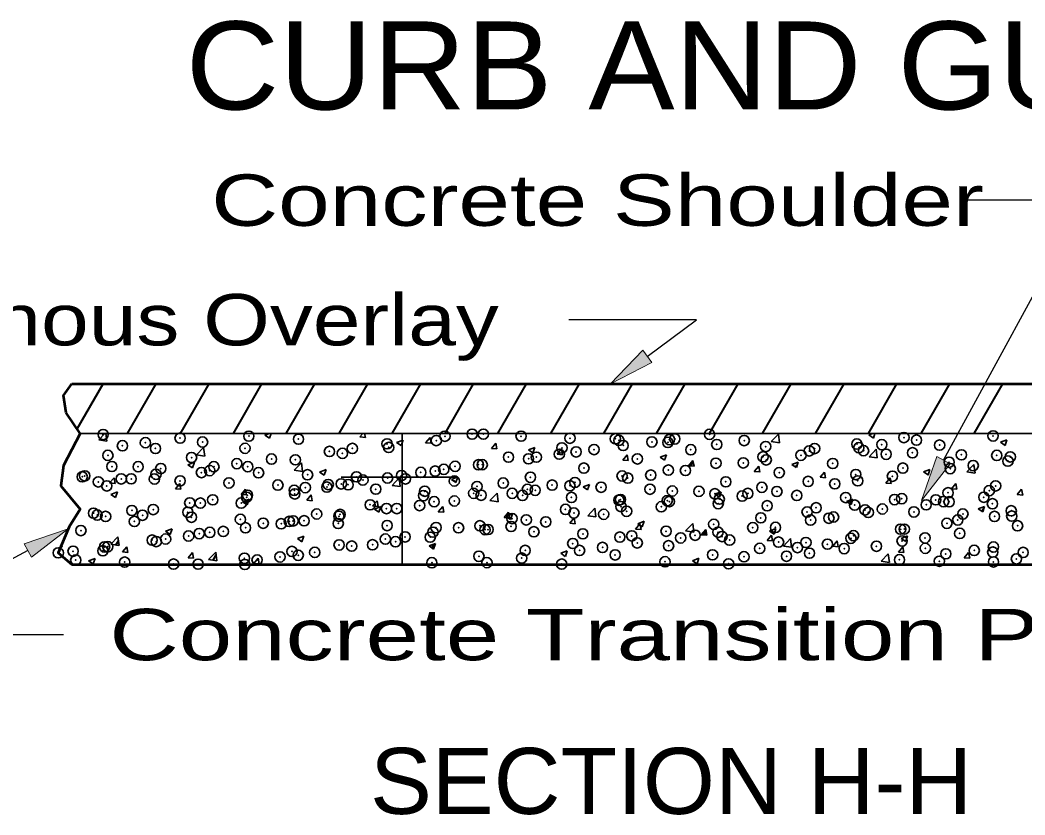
# Model space of a CAD drawing. Extents: x 14 to 49.3, y 28 to 50.
# Drawn here: x 25.568 to 28.309, y 37.153 to 39.319 of the extents above; entities that cross this region are included whole.
import ezdxf

# ---------------------------------------------------------------- set-up
doc = ezdxf.new("R2010")
doc.units = 0
doc.header["$LTSCALE"] = 0.056
doc.header["$PDMODE"] = 32
doc.header["$PDSIZE"] = 0.028
doc.layers.add('1', color=7, linetype='Continuous', lineweight=35)
doc.layers.add('3', color=7, linetype='Continuous', lineweight=13)

msp = doc.modelspace()

# ---------------------------------------------------------------- hatches: boundary and pattern name
at = {"layer": '3'}
for points in [[(27.29108, 38.38558), (27.26625, 38.419), (27.17842, 38.32767), (27.17842, 38.32767)], [(28.10483, 38.1095), (28.06825, 38.12942), (28.02667, 38.00975), (28.02667, 38.00975)], [(25.57942, 37.89183), (25.59917, 37.85517), (25.69933, 37.93283), (25.69933, 37.93283)]]:
    msp.add_hatch(color=256, dxfattribs=at).paths.add_polyline_path(points)

# ---------------------------------------------------------------- linework, layer by layer
at = {"layer": '1', "lineweight": 53}
msp.add_line((25.70917, 38.32767), (29.27625, 38.32767), dxfattribs=at)
at = {"layer": '1', "lineweight": 40}
for p, q in [((25.72367, 38.20467), (25.79467, 38.32767)), ((25.861, 38.1925), (25.939, 38.32767)), ((26.00533, 38.1925), (26.08333, 38.32767)), ((26.14967, 38.1925), (26.22767, 38.32767)), ((26.294, 38.1925), (26.372, 38.32767)), ((26.43833, 38.1925), (26.51633, 38.32767)), ((26.58267, 38.1925), (26.66067, 38.32767)), ((26.727, 38.1925), (26.805, 38.32767)), ((26.87133, 38.1925), (26.94933, 38.32767)), ((27.01567, 38.1925), (27.09367, 38.32767)), ((27.16, 38.1925), (27.238, 38.32767)), ((27.30433, 38.1925), (27.38233, 38.32767)), ((27.44875, 38.1925), (27.52667, 38.32767)), ((27.59308, 38.1925), (27.67108, 38.32767)), ((27.73742, 38.1925), (27.81542, 38.32767)), ((27.88175, 38.1925), (27.95975, 38.32767)), ((28.02608, 38.1925), (28.10408, 38.32767)), ((28.17042, 38.1925), (28.24842, 38.32767)), ((27.39742, 38.10375), (27.404, 38.11517)), ((27.684, 38.10008), (27.688, 38.10708)), ((26.18325, 38.00075), (26.18975, 38.012)), ((28.19192, 37.97983), (28.19767, 37.98983)), ((27.43317, 37.91558), (27.439, 37.92567)), ((25.8295, 37.888), (25.83625, 37.89958)), ((26.69117, 37.8805), (26.69725, 37.89092)), ((26.09442, 37.84692), (26.10267, 37.86117))]:
    msp.add_line(p, q, dxfattribs=at)
at = {"layer": '1'}
for p, q in [((29.27625, 38.1925), (25.73192, 38.1925)), ((25.78233, 38.17508), (25.79908, 38.1925)), ((25.80458, 38.17158), (25.80217, 38.1925)), ((26.23583, 38.18767), (26.24858, 38.1925)), ((26.23583, 38.18767), (26.24825, 38.17925)), ((26.24825, 38.17925), (26.25275, 38.1925)), ((26.49475, 38.18275), (26.503, 38.1925)), ((26.49475, 38.18275), (26.50967, 38.18142)), ((26.50967, 38.18142), (26.50767, 38.1925)), ((26.61042, 38.1925), (26.61042, 37.83492)), ((26.67408, 38.16708), (26.68608, 38.18142)), ((26.689, 38.16575), (26.68608, 38.18142)), ((27.61683, 38.17033), (27.63633, 38.19058)), ((27.63908, 38.16683), (27.63633, 38.19058)), ((27.883, 38.18817), (27.89433, 38.1925)), ((27.883, 38.18817), (27.89542, 38.17975)), ((27.89542, 38.17975), (27.89975, 38.1925)), ((25.78233, 38.17508), (25.80458, 38.17158)), ((26.04917, 38.13367), (26.06858, 38.154)), ((26.07142, 38.13025), (26.06858, 38.154)), ((26.59508, 38.16758), (26.61258, 38.17433)), ((26.59508, 38.16758), (26.6075, 38.15925)), ((26.6075, 38.15917), (26.61258, 38.17433)), ((26.67408, 38.16708), (26.689, 38.16575)), ((26.85342, 38.15133), (26.86542, 38.16575)), ((26.86833, 38.15), (26.86542, 38.16575)), ((26.95433, 38.14758), (26.97183, 38.15433)), ((26.96683, 38.13917), (26.97192, 38.15433)), ((27.61683, 38.17033), (27.63908, 38.16683)), ((28.24225, 38.16817), (28.25975, 38.17483)), ((28.24225, 38.16817), (28.25467, 38.15975)), ((28.25475, 38.15975), (28.25975, 38.17483)), ((26.04917, 38.13367), (26.07133, 38.13025)), ((26.85342, 38.15133), (26.86833, 38.15008)), ((26.95433, 38.14758), (26.96683, 38.13917)), ((27.03267, 38.13567), (27.04475, 38.15)), ((27.03267, 38.13567), (27.04767, 38.13433)), ((27.04767, 38.13433), (27.04475, 38.15)), ((27.212, 38.12), (27.22408, 38.13433)), ((27.22692, 38.11867), (27.22408, 38.13433)), ((27.31367, 38.12758), (27.33117, 38.13425)), ((27.31367, 38.12758), (27.32608, 38.11917)), ((27.32608, 38.11917), (27.33117, 38.13425)), ((27.88367, 38.12892), (27.90317, 38.14925)), ((27.88367, 38.12892), (27.90592, 38.1255)), ((27.90592, 38.1255), (27.90317, 38.14925)), ((26.02575, 38.107), (26.04325, 38.11375)), ((26.02575, 38.107), (26.03817, 38.09858)), ((26.03817, 38.09858), (26.04325, 38.11367)), ((26.03817, 38.09858), (26.04325, 38.11367)), ((26.31592, 38.09233), (26.33542, 38.11258)), ((26.33817, 38.08883), (26.33542, 38.11258)), ((27.212, 38.12), (27.22692, 38.11867)), ((27.39133, 38.10425), (27.40333, 38.11867)), ((27.39133, 38.10425), (27.40625, 38.103)), ((27.40625, 38.103), (27.40342, 38.11867)), ((27.57067, 38.08858), (27.58267, 38.103)), ((27.58558, 38.08725), (27.58267, 38.10292)), ((27.67292, 38.1075), (27.69042, 38.11425)), ((27.67292, 38.1075), (27.68533, 38.09917)), ((27.68542, 38.09917), (27.69042, 38.11425)), ((28.1505, 38.08758), (28.16992, 38.10783)), ((28.17275, 38.08408), (28.16992, 38.10783)), ((25.81217, 38.05742), (25.82425, 38.07183)), ((25.82708, 38.05608), (25.82425, 38.07175)), ((26.31592, 38.09233), (26.33817, 38.08883)), ((26.385, 38.087), (26.4025, 38.09367)), ((26.385, 38.087), (26.3975, 38.07858)), ((26.3975, 38.07858), (26.40258, 38.09367)), ((26.44383, 38.07333), (26.76192, 38.07333)), ((26.74433, 38.06692), (26.76183, 38.07367)), ((26.75675, 38.05858), (26.76183, 38.07367)), ((27.57067, 38.08858), (27.58558, 38.08733)), ((27.74992, 38.07292), (27.762, 38.08725)), ((27.74992, 38.07292), (27.76492, 38.07158)), ((27.76492, 38.07158), (27.762, 38.08725)), ((27.92925, 38.05725), (27.94133, 38.07158)), ((27.94425, 38.05592), (27.94133, 38.07158)), ((28.03225, 38.0875), (28.04975, 38.09425)), ((28.03225, 38.0875), (28.04467, 38.07917)), ((28.04467, 38.07908), (28.04975, 38.09425)), ((28.1505, 38.08758), (28.17267, 38.08408)), ((25.81217, 38.05742), (25.82708, 38.05617)), ((25.9915, 38.04175), (26.0035, 38.05608)), ((26.00642, 38.04042), (26.00358, 38.05608)), ((26.58275, 38.05092), (26.60225, 38.07125)), ((26.58275, 38.05092), (26.605, 38.0475)), ((26.605, 38.0475), (26.60225, 38.07125)), ((26.74433, 38.06692), (26.75675, 38.05858)), ((27.10358, 38.04692), (27.12108, 38.05367)), ((27.10358, 38.04692), (27.116, 38.0385)), ((27.116, 38.0385), (27.12108, 38.05367)), ((27.92925, 38.05725), (27.94425, 38.05592)), ((28.10858, 38.0415), (28.12067, 38.05592)), ((28.1235, 38.04025), (28.12067, 38.05592)), ((25.81567, 38.02633), (25.83317, 38.03308)), ((25.81567, 38.02633), (25.82817, 38.018)), ((25.82817, 38.018), (25.83317, 38.03308)), ((25.9915, 38.04175), (26.00642, 38.04042)), ((26.17083, 38.02608), (26.18283, 38.04042)), ((26.17083, 38.02608), (26.18575, 38.02475)), ((26.18575, 38.02475), (26.18283, 38.04042)), ((26.35008, 38.01033), (26.36217, 38.02475)), ((26.36508, 38.00908), (26.36217, 38.02475)), ((26.84958, 38.00958), (26.869, 38.02983)), ((26.87183, 38.00608), (26.86908, 38.02983)), ((27.46292, 38.02692), (27.48042, 38.03358)), ((27.46292, 38.02692), (27.47533, 38.0185)), ((27.47533, 38.0185), (27.48042, 38.03358)), ((28.10858, 38.0415), (28.1235, 38.04025)), ((28.28792, 38.02583), (28.29992, 38.04025)), ((28.28792, 38.02583), (28.30283, 38.02458)), ((28.30283, 38.0245), (28.29992, 38.04017)), ((26.175, 38.00633), (26.1925, 38.01308)), ((26.175, 38.00633), (26.18742, 37.99792)), ((26.18742, 37.99792), (26.1925, 38.01308)), ((26.35008, 38.01033), (26.36508, 38.00908)), ((26.52942, 37.99467), (26.5415, 38.00908)), ((26.52942, 37.99467), (26.54442, 37.99342)), ((26.53425, 37.98633), (26.55175, 37.993)), ((26.54442, 37.99333), (26.5415, 38.009)), ((26.54667, 37.97792), (26.55175, 37.993)), ((26.70875, 37.979), (26.72083, 37.99333)), ((26.72367, 37.97767), (26.72083, 37.99333)), ((26.84958, 38.00958), (26.87183, 38.00608)), ((27.82217, 38.00692), (27.83967, 38.01358)), ((27.82217, 38.00692), (27.83458, 37.9985)), ((27.83458, 37.9985), (27.83967, 38.01358)), ((28.18142, 37.98683), (28.19892, 37.99358)), ((28.19392, 37.9785), (28.19892, 37.99358)), ((26.53425, 37.98633), (26.54667, 37.97792)), ((26.70875, 37.979), (26.72367, 37.97767)), ((26.88808, 37.96333), (26.90008, 37.97767)), ((26.88808, 37.96333), (26.903, 37.962)), ((26.8935, 37.96633), (26.91108, 37.973)), ((26.8935, 37.96633), (26.906, 37.95792)), ((26.903, 37.962), (26.90008, 37.97767)), ((26.906, 37.95792), (26.91108, 37.973)), ((27.06742, 37.94758), (27.07942, 37.962)), ((27.08233, 37.94633), (27.07942, 37.962)), ((27.11642, 37.96817), (27.13583, 37.9885)), ((27.11642, 37.96817), (27.13858, 37.96475)), ((27.13858, 37.96475), (27.13583, 37.98842)), ((28.18142, 37.98683), (28.19392, 37.9785)), ((27.06742, 37.94758), (27.08233, 37.94633)), ((27.24667, 37.93192), (27.25875, 37.94633)), ((27.25283, 37.94625), (27.27033, 37.953)), ((27.25283, 37.94625), (27.26525, 37.93792)), ((27.26167, 37.93058), (27.25875, 37.94625)), ((27.26525, 37.93792), (27.27033, 37.953)), ((27.38317, 37.92675), (27.40267, 37.94708)), ((27.40542, 37.92333), (27.40267, 37.94708)), ((25.8155, 37.89017), (25.83492, 37.91042)), ((25.83775, 37.88667), (25.83492, 37.91042)), ((25.96492, 37.92567), (25.98242, 37.93242)), ((25.96492, 37.92567), (25.97733, 37.91733)), ((25.97733, 37.91733), (25.98242, 37.93242)), ((26.32417, 37.90567), (26.34167, 37.91242)), ((26.33667, 37.89725), (26.34175, 37.91242)), ((27.24667, 37.93192), (27.26167, 37.93058)), ((27.38317, 37.92675), (27.40542, 37.92333)), ((27.426, 37.91625), (27.43808, 37.93058)), ((27.426, 37.91625), (27.44092, 37.91492)), ((27.441, 37.91492), (27.43808, 37.93058)), ((27.60533, 37.90058), (27.61742, 37.91492)), ((27.61208, 37.92625), (27.62958, 37.933)), ((27.61208, 37.92625), (27.6245, 37.91783)), ((27.62025, 37.89925), (27.61742, 37.91492)), ((27.62458, 37.91783), (27.62958, 37.933)), ((27.97142, 37.90625), (27.98892, 37.91292)), ((27.98383, 37.89783), (27.98892, 37.91292)), ((25.67867, 37.88408), (25.6825, 37.88375)), ((25.6825, 37.88375), (25.68125, 37.89033)), ((25.8155, 37.89017), (25.83767, 37.88675)), ((25.84683, 37.86942), (25.85892, 37.88375)), ((25.86183, 37.86808), (25.85892, 37.88375)), ((26.32417, 37.90567), (26.33667, 37.89733)), ((26.6835, 37.88567), (26.701, 37.89242)), ((26.6835, 37.88567), (26.69592, 37.87725)), ((26.69592, 37.87725), (26.701, 37.89233)), ((27.60533, 37.90058), (27.62025, 37.89925)), ((27.65, 37.88542), (27.6695, 37.90567)), ((27.65, 37.88542), (27.67225, 37.882)), ((27.67225, 37.88192), (27.6695, 37.90567)), ((27.78467, 37.88483), (27.79667, 37.89925)), ((27.78467, 37.88483), (27.79958, 37.88358)), ((27.79958, 37.88358), (27.79667, 37.89925)), ((27.96392, 37.86917), (27.976, 37.88358)), ((27.97142, 37.90625), (27.98383, 37.89783)), ((27.97892, 37.86783), (27.976, 37.8835)), ((25.84683, 37.86942), (25.86183, 37.86808)), ((26.02617, 37.85367), (26.03825, 37.86808)), ((26.02617, 37.85367), (26.04108, 37.85242)), ((26.04117, 37.85242), (26.03825, 37.86808)), ((26.08225, 37.84875), (26.10175, 37.86908)), ((26.1045, 37.84533), (26.10175, 37.86908)), ((26.2055, 37.838), (26.21758, 37.85233)), ((26.22042, 37.83667), (26.21758, 37.85233)), ((27.04275, 37.86567), (27.06025, 37.87233)), ((27.04275, 37.86567), (27.05517, 37.85725)), ((27.05525, 37.85725), (27.06025, 37.87233)), ((27.40208, 37.84558), (27.41958, 37.85233)), ((27.4145, 37.83725), (27.41958, 37.85233)), ((27.91683, 37.844), (27.93625, 37.86433)), ((27.93908, 37.84058), (27.93625, 37.86433)), ((27.96392, 37.86917), (27.97892, 37.86783)), ((28.14325, 37.8535), (28.15533, 37.86783)), ((28.14325, 37.8535), (28.15825, 37.85217)), ((28.15825, 37.85217), (28.15533, 37.86783)), ((25.75483, 37.84508), (25.77233, 37.85175)), ((25.75483, 37.84508), (25.76733, 37.83667)), ((25.76733, 37.83667), (25.77242, 37.85175)), ((26.08225, 37.84875), (26.1045, 37.84533)), ((26.2055, 37.838), (26.22042, 37.83667)), ((26.39542, 37.83492), (26.39683, 37.83667)), ((26.39717, 37.83492), (26.39683, 37.83667)), ((27.40208, 37.84558), (27.4145, 37.83725)), ((27.40208, 37.84558), (27.4145, 37.83725)), ((27.91683, 37.844), (27.939, 37.84058))]:
    msp.add_line(p, q, dxfattribs=at)
at = {"layer": '1', "lineweight": 53}
for points in [[(25.73192, 38.1925), (25.694, 38.24817), (25.68642, 38.29583), (25.70917, 38.32767)], [(25.73192, 38.1925), (25.68642, 38.10517), (25.67892, 38.0495), (25.73192, 37.98592), (25.70158, 37.93825), (25.67133, 37.86675), (25.70917, 37.83492)], [(25.70917, 37.83492), (29.27625, 37.83492), (29.27625, 38.1925)]]:
    msp.add_lwpolyline(points, dxfattribs=at)
at = {"layer": '1'}
for p in [(25.7945, 38.18925), (25.90967, 38.16717), (26.00442, 38.17967), (26.06567, 38.169), (26.19192, 38.185), (26.32733, 38.17683), (26.70325, 38.17292), (26.72683, 38.18483), (26.801, 38.1905), (26.83158, 38.1905), (26.9345, 38.18492), (27.06792, 38.17925), (27.19175, 38.17783), (27.20142, 38.17358), (27.29133, 38.16917), (27.33483, 38.168), (27.33933, 38.17558), (27.35392, 38.17742), (27.44858, 38.18992), (27.54325, 38.173), (27.97892, 38.18108), (28.01317, 38.17425), (28.22192, 38.18558), (25.84708, 38.15892), (25.93725, 38.15142), (26.1815, 38.15183), (26.41167, 38.14333), (26.47425, 38.15158), (26.56892, 38.164), (26.57333, 38.15417), (27.046, 38.15283), (27.08467, 38.142), (27.1335, 38.14842), (27.213, 38.15958), (27.3975, 38.148), (27.46833, 38.16233), (27.60175, 38.15667), (27.72075, 38.14475), (27.73525, 38.15108), (27.85058, 38.1635), (27.85592, 38.15358), (27.86867, 38.14542), (27.9185, 38.16183), (28.00217, 38.13975), (28.07617, 38.16058), (25.80742, 38.13267), (26.03575, 38.12675), (26.25375, 38.12258), (26.31875, 38.1205), (26.44708, 38.13817), (26.90017, 38.12775), (26.95483, 38.12325), (26.97617, 38.12775), (27.03875, 38.13592), (27.25167, 38.12292), (27.5945, 38.12875), (27.60333, 38.12033), (27.698, 38.13283), (27.93033, 38.13558), (28.10217, 38.11392), (28.13558, 38.13417), (28.232, 38.13258), (28.26258, 38.11717), (28.26908, 38.1285), (25.81817, 38.10225), (25.88992, 38.10175), (25.95158, 38.09658), (26.06258, 38.08575), (26.08508, 38.091), (26.0965, 38.10183), (26.15908, 38.11008), (26.18892, 38.10175), (26.2185, 38.08533), (26.661, 38.08625), (26.70017, 38.08967), (26.72358, 38.0945), (26.75442, 38.10275), (26.81833, 38.10692), (26.8285, 38.10725), (27.10592, 38.09792), (27.33625, 38.09242), (27.38283, 38.09133), (27.46608, 38.11117), (27.54075, 38.11208), (27.63875, 38.0855), (27.78458, 38.1105), (27.97592, 38.09783), (28.10525, 38.0965), (28.16783, 38.10467), (25.73742, 38.07433), (25.74417, 38.07675), (25.78133, 38.06033), (25.84392, 38.06858), (25.87092, 38.06867), (25.93425, 38.06817), (25.93858, 38.08108), (26.00433, 38.063), (26.13775, 38.05742), (26.352, 38.07967), (26.48542, 38.07408), (26.50317, 38.06542), (26.57033, 38.07092), (26.60858, 38.07775), (26.61892, 38.06842), (26.75233, 38.06275), (26.96008, 38.07292), (27.08158, 38.05875), (27.21, 38.07642), (27.22558, 38.07058), (27.28817, 38.07883), (27.493, 38.0605), (27.71767, 38.0615), (27.84758, 38.08025), (27.85275, 38.06325), (27.94742, 38.07567), (25.80442, 38.04942), (26.27125, 38.05175), (26.31567, 38.03733), (26.34592, 38.04475), (26.40467, 38.04608), (26.4085, 38.053), (26.44408, 38.05492), (26.46283, 38.05267), (26.53817, 38.0405), (26.67158, 38.03483), (26.81433, 38.04783), (26.88583, 38.05717), (26.95175, 38.04008), (26.973, 38.03733), (27.01925, 38.0515), (27.06767, 38.04983), (27.15275, 38.04583), (27.28617, 38.04025), (27.34717, 38.03542), (27.41967, 38.03458), (27.59142, 38.0455), (27.63225, 38.03417), (27.79017, 38.055), (28.09917, 38.03067), (28.21167, 38.03642), (28.229, 38.04942), (26.03075, 38.00325), (26.05958, 38.00258), (26.09333, 38.0115), (26.17125, 38.00267), (26.18583, 38.01858), (26.188, 38.02392), (26.317, 38.02767), (26.6685, 38.02283), (26.69717, 38.00642), (26.7525, 38.00833), (26.80508, 38.02917), (26.8255, 38.024), (26.91042, 38.02908), (26.9385, 38.02358), (27.072, 38.01792), (27.20133, 38.01042), (27.20542, 38.01225), (27.33325, 38.00917), (27.33892, 38.00667), (27.46308, 38.02792), (27.475, 38.0135), (27.53758, 38.02175), (27.55308, 38.02892), (27.68658, 38.02333), (27.82, 38.01767), (27.95342, 38.012), (27.97283, 38.01467), (28.06583, 38.01142), (28.08692, 38.00642), (28.10208, 38.00608), (28.19675, 38.01858), (25.76842, 37.97517), (25.87283, 37.98242), (25.93125, 37.985), (26.02542, 37.97758), (26.52275, 37.99783), (26.56725, 37.98767), (26.59525, 37.98758), (26.65783, 37.99583), (27.05558, 37.98542), (27.07858, 37.97558), (27.20692, 37.99317), (27.22242, 37.98025), (27.31708, 37.99267), (27.47233, 38.001), (27.60583, 37.99533), (27.71467, 37.97833), (27.73925, 37.98975), (27.8445, 37.99708), (27.87275, 37.98408), (27.88167, 37.97708), (27.92, 37.98642), (28.00617, 37.97842), (28.0395, 37.99783), (28.22033, 38.00075), (28.2715, 37.98158), (25.77817, 37.97), (25.80133, 37.96625), (25.87958, 37.95258), (25.90192, 37.9695), (26.03533, 37.96392), (26.16883, 37.95825), (26.23108, 37.94775), (26.30225, 37.95258), (26.31267, 37.95408), (26.34267, 37.95433), (26.37692, 37.97275), (26.43742, 37.96683), (26.441, 37.97167), (26.90975, 37.96033), (26.94875, 37.95683), (27.00192, 37.95125), (27.15983, 37.972), (27.58842, 37.96233), (27.72433, 37.95633), (27.77425, 37.96133), (27.78692, 37.96458), (28.12575, 37.9565), (28.13967, 37.97283), (28.22592, 37.96617), (28.27308, 37.96717), (25.73383, 37.92758), (26.08533, 37.92275), (26.12225, 37.92533), (26.18283, 37.93533), (26.28008, 37.94617), (26.43575, 37.947), (26.56917, 37.94133), (26.69408, 37.92325), (26.70258, 37.93567), (26.764, 37.93533), (26.82242, 37.94083), (26.83608, 37.93008), (26.84467, 37.9305), (26.90725, 37.93875), (26.9695, 37.92442), (27.33017, 37.92592), (27.46, 37.94467), (27.47175, 37.92308), (27.5665, 37.93558), (27.62842, 37.93633), (27.96983, 37.93142), (27.97992, 37.9315), (28.09608, 37.94742), (28.28892, 37.94075), (25.92817, 37.90175), (25.9395, 37.89767), (25.965, 37.90467), (26.02758, 37.91283), (26.0565, 37.91933), (26.56425, 37.9045), (26.59208, 37.89725), (26.61817, 37.91033), (26.68675, 37.90975), (27.103, 37.91875), (27.20392, 37.90992), (27.23642, 37.91317), (27.25133, 37.89408), (27.36992, 37.9075), (27.40917, 37.91492), (27.48267, 37.91133), (27.50333, 37.90183), (27.63683, 37.89625), (27.71158, 37.89508), (27.83417, 37.9065), (27.8415, 37.91383), (27.97375, 37.89925), (28.03633, 37.9075), (28.131, 37.92), (25.67208, 37.867), (25.71242, 37.87142), (25.79375, 37.87267), (25.79833, 37.883), (25.80708, 37.88383), (26.30958, 37.87083), (26.37158, 37.86825), (26.438, 37.8885), (26.47242, 37.88533), (26.5295, 37.889), (26.94567, 37.87358), (27.0755, 37.89233), (27.09408, 37.87342), (27.15667, 37.88167), (27.33683, 37.88625), (27.58533, 37.87908), (27.68833, 37.88142), (27.72117, 37.866), (27.77025, 37.89058), (27.81583, 37.8785), (27.90375, 37.88492), (28.03717, 37.87933), (28.17067, 37.87367), (28.22125, 37.869), (28.22292, 37.88292), (28.30408, 37.868), (25.71975, 37.84742), (25.85317, 37.84175), (26.17975, 37.85208), (26.21433, 37.8475), (26.27692, 37.85575), (26.32658, 37.86025), (26.69108, 37.84), (26.81942, 37.85758), (26.8415, 37.84017), (26.93617, 37.85258), (27.19108, 37.86125), (27.32717, 37.84275), (27.457, 37.8615), (27.54258, 37.85642), (27.65858, 37.85775), (27.96675, 37.84817), (28.07542, 37.844), (28.09308, 37.86417), (28.22317, 37.84217), (28.28575, 37.85042), (25.98667, 37.83617), (26.0535, 37.83608), (26.18083, 37.83525), (27.04525, 37.83625), (27.50067, 37.837)]:
    msp.add_point(p, dxfattribs=at)
at = {"layer": '3', "lineweight": 25}
for points in [[(28.08658, 38.1195), (28.4735, 38.82825), (28.14783, 38.82825)], [(27.27867, 38.40225), (27.41317, 38.5025), (27.06483, 38.5025)], [(25.58925, 37.8735), (25.16392, 37.64425), (25.68642, 37.64425)]]:
    msp.add_lwpolyline(points, dxfattribs=at)
at = {"layer": '3'}
for points in [[(27.29108, 38.38558), (27.26625, 38.419), (27.17842, 38.32767), (27.17842, 38.32767)], [(28.10483, 38.1095), (28.06825, 38.12942), (28.02667, 38.00975), (28.02667, 38.00975)], [(25.57942, 37.89183), (25.59917, 37.85517), (25.69933, 37.93283), (25.69933, 37.93283)]]:
    msp.add_lwpolyline(points, close=True, dxfattribs=at)

# ---------------------------------------------------------------- texts
for s, height, width, p in [('CURB AND GUTTER', 0.24, 1.1, (26.01958, 39.07542)), ('Concrete Shoulder', 0.14, 1.35, (26.08942, 38.75825)), ('2" Bituminous Overlay', 0.14, 1.25, (24.5665, 38.4325)), ('Concrete Transition Pavement', 0.14, 1.4, (25.81142, 37.57425)), ('SECTION H-H', 0.18, 1.05, (26.5225, 37.15525))]:
    msp.add_text(s, height=height, dxfattribs=dict(at, width=width)).set_placement(p)

doc.saveas('drawing.dxf')
